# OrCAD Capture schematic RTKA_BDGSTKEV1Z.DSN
size Custom
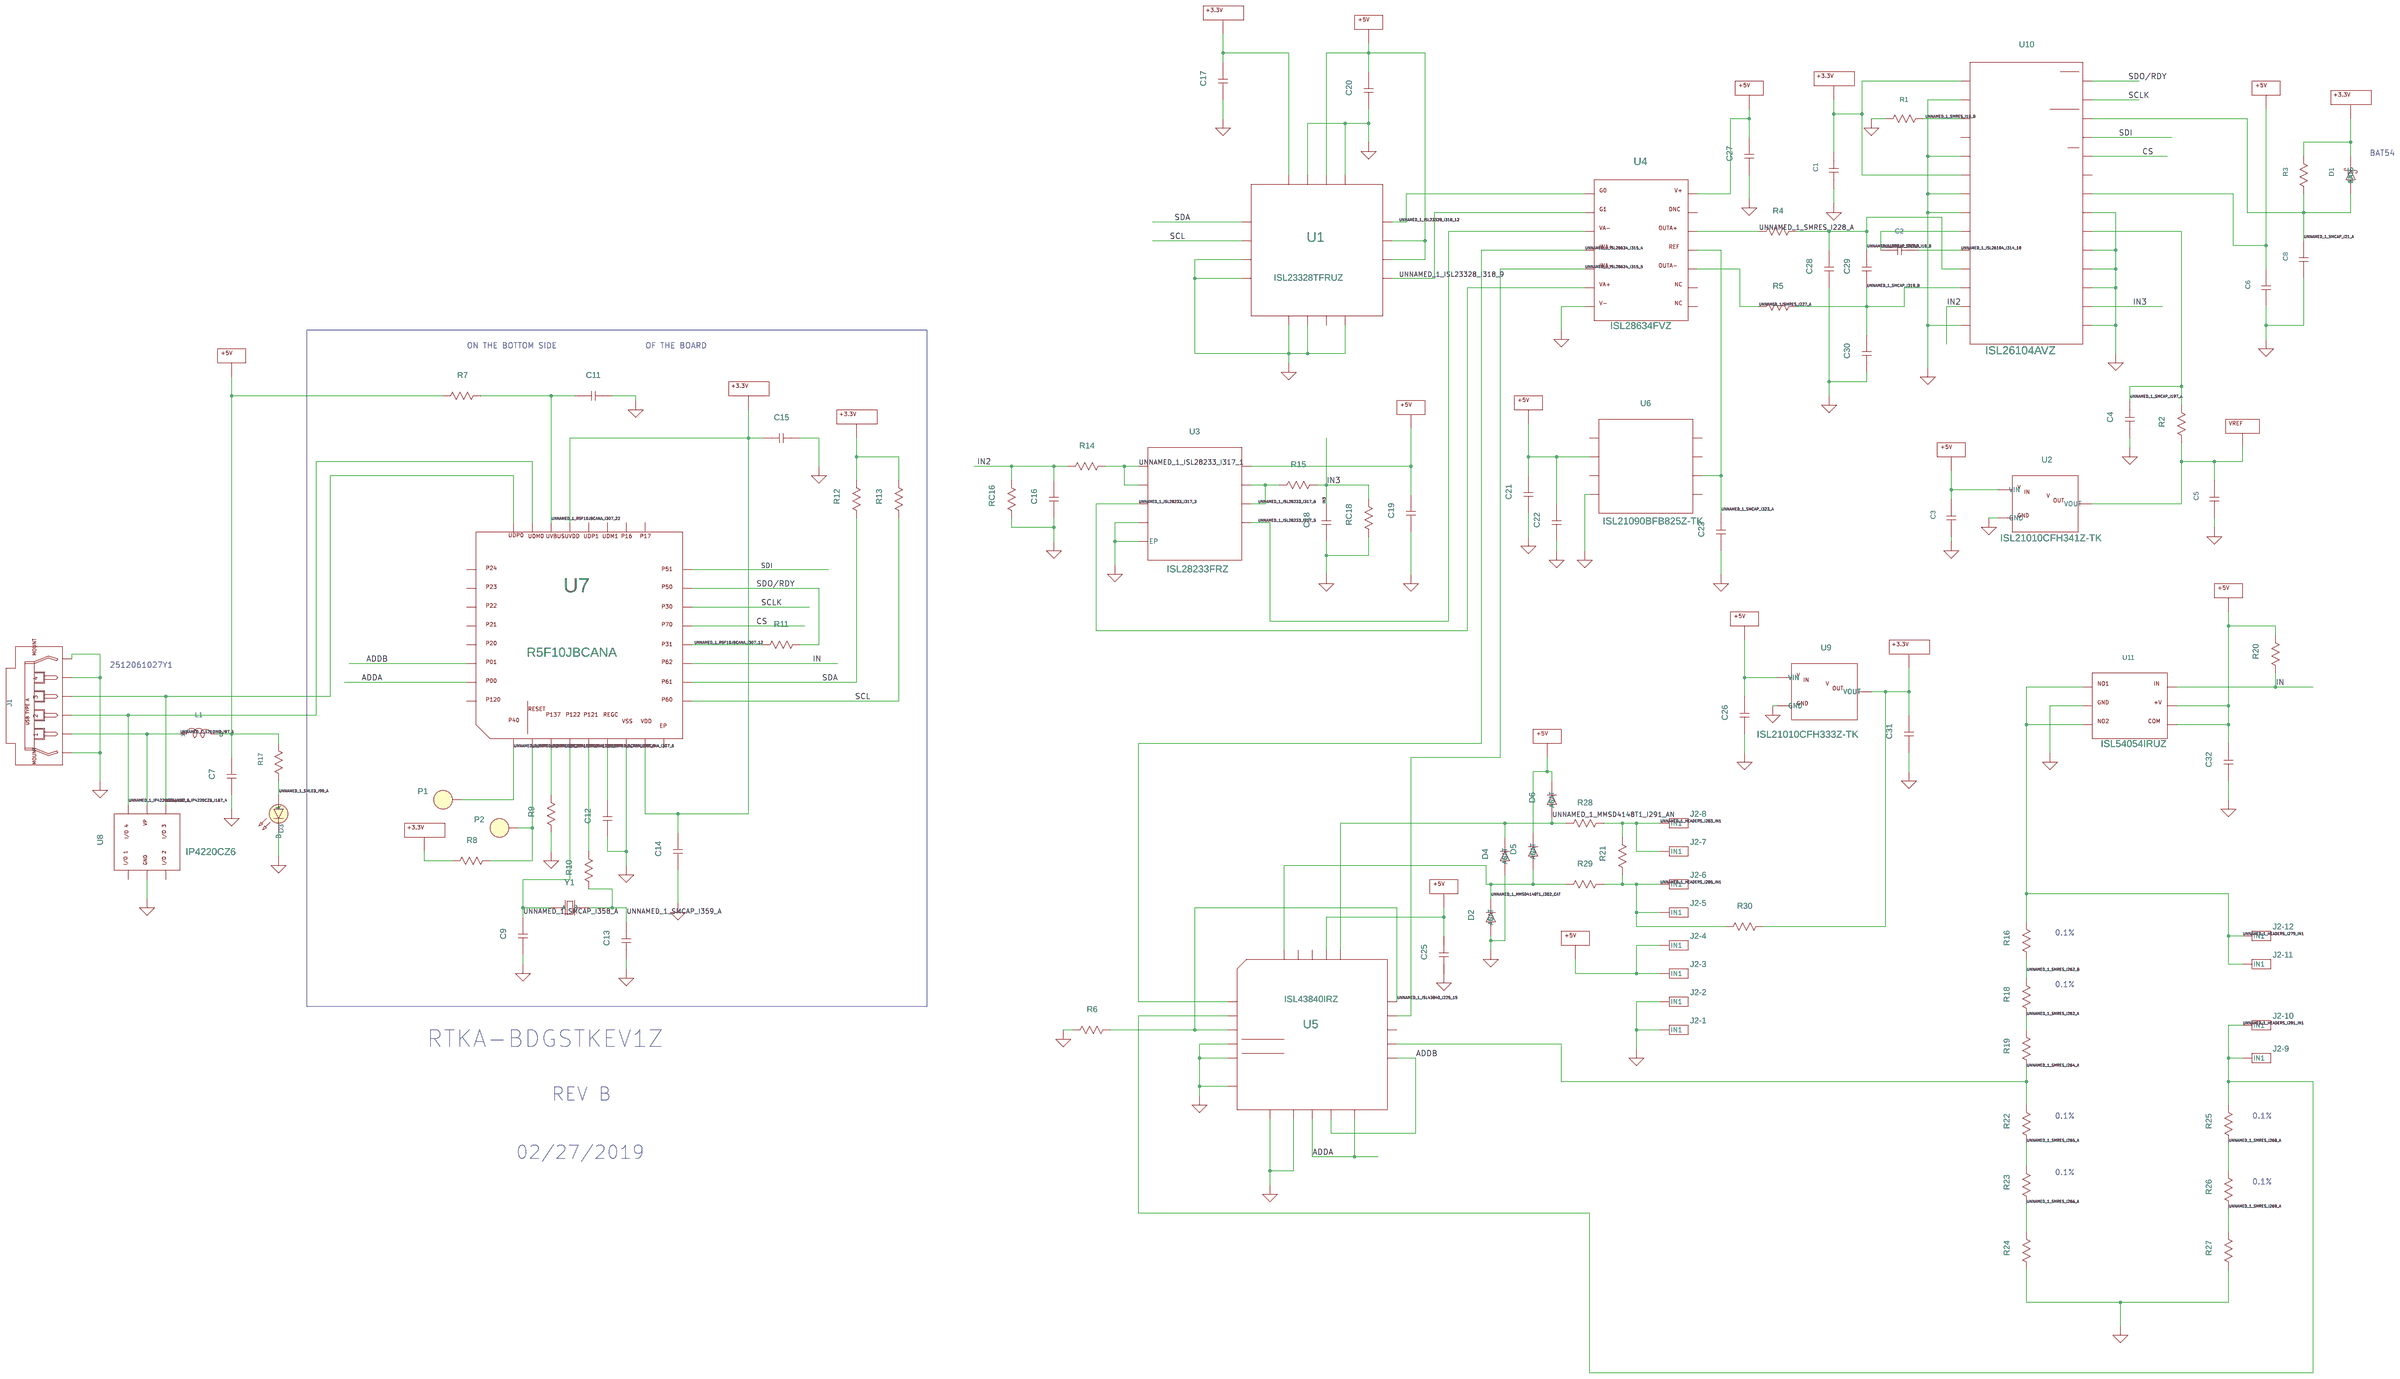
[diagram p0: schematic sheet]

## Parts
C1  0.01UF  [CAP_0402]
C2  0.1UF  [CAP_0402]
C3  1UF  [CAP_0603]
C4  10UF  [CAP_1206]
C5  0.1UF  [CAP_0402]
C6  0.01UF  [CAP_0402]
C7  4.7UF  [CAP_0805]
C8  2.2UF  [CAP_0805]
C9  10PF  [CAP_0402]
C11  1UF  [CAP_0603]
C12  1UF  [CAP_0603]
C13  10PF  [CAP_0402]
C14  0.1UF  [CAP_0402]
C15  0.33UF  [CAP_0603]
C16  0.1UF  [CAP_0402]
C17  0.1UF  [CAP_0402]
C18  0.1UF  [CAP_0402]
C19  0.1UF  [CAP_0402]
C20  0.1UF  [CAP_0402]
C21  10UF  [CAP_0805]
C22  0.1UF  [CAP_0402]
C23  0.1UF  [CAP_0402]
C25  0.01UF  [CAP_0402]
C26  1UF  [CAP_0603]
C27  0.1UF  [CAP_0402]
C28  0.1UF  [CAP_0402]
C29  0.1UF  [CAP_0402]
C30  0.1UF  [CAP_0402]
C31  0.1UF  [CAP_0402]
C32  0.1UF  [CAP_0402]
D1  SM_SCHOTTKY  [SOT23]
D2  MMSD4148T1  [SOD123]
D3  SM_LED  [DIA_LED1206]
D4  MMSD4148T1  [SOD123]
D5  MMSD4148T1  [SOD123]
D6  MMSD4148T1  [SOD123]
J1  USB_A  [CON_USB_MOLEX_480371000]
J2  HEADERS  [CON_HDR_90151-3X12]  (sections -1,-10,-11,-12,-2,-3,-4,-5,-6,-7,-8,-9)
L1  TBD  [SM1210]
P1  SINGLE  [PAD-50]
P2  SINGLE  [PAD-50]
R1  0  [RES_0402]
R2  100  [RES_0402]
R3  1K  [RES_0402]
R4  49.9  [RES_0402]
R5  49.9  [RES_0402]
R6  0  [RES_0402]
R7  100  [RES_0402]
R8  10K  [RES_0402]
R9  10K  [RES_0402]
R10  221  [RES_0402]
R11  0  [RES_0402]
R12  4.99K  [RES_0402]
R13  4.99K  [RES_0402]
R14  49.9  [RES_0402]
R15  49.9  [RES_0402]
R16  249  [RES_0805]
R17  3K  [RES_0603]
R18  100  [RES_0805]
R19  1  [RES_0805]
R20  4.99K  [RES_0402]
R21  499  [RES_0805]
R22  249  [RES_0805]
R23  100  [RES_0805]
R24  1  [RES_0805]
R25  249  [RES_0805]
R26  100  [RES_0805]
R27  1  [RES_0805]
R28  10K  [RES_0402]
R29  10K  [RES_0402]
R30  0  [RES_0402]
RC16  4.99K  [RES_0402]
RC18  4.99K  [RES_0402]
U1  ISL23328  [UTQFN16_102X71_157]
U2  ISL21010  [SOT23-3]
U3  ISL28233  [DFN8_118X118_256_EP2]
U4  ISL28634  [TSSOP14_173_256_V2]
U5  ISL43840  [QFN20_157X157_197_EP]
U6  ISL21090  [SOIC8_150_50E]
U7  R5F10JBCANA  [QFN32_197X197_197_EPA2]
U8  IP4220CZ6  [SOT457]
U9  ISL21010  [SOT23-3]
U10  ISL26104  [TSSOP28_173_256]
U11  ISL54054  [UTDFN6_47X39_157_A]
Y1  SM_CRYSTAL  [XTAL_NX5032GA]

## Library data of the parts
C1 = SM_CAP: CDS_LIB: capacitors; CDS_PART_NAME: SM_CAP_0402-H1044-00103-16V10,B; CDS_PHYS_PART_NAME: SM_CAP_0402-H1044-00103-16V10,B; DRAWING: @ISLTHERMO_STKEV1Z_LIB.RTKA_BDGSTKEV1Z(SCH_1):PAGE1; PACK_TYPE: 0402; PART_NUMBER: H1044-00103-16V10; PHYS_PAGE: 1; RATED_VOLTAGE: 16V; ROT: 1; TOLERANCE: 10%; VER: 1; XY: (5000,4625)
C2 = SM_CAP: CDS_LIB: capacitors; CDS_PART_NAME: SM_CAP_0402-H1044-00104-16V10,B; CDS_PHYS_PART_NAME: SM_CAP_0402-H1044-00104-16V10,B; DRAWING: @ISLTHERMO_STKEV1Z_LIB.RTKA_BDGSTKEV1Z(SCH_1):PAGE1; PACK_TYPE: 0402; PART_NUMBER: H1044-00104-16V10; PHYS_PAGE: 1; RATED_VOLTAGE: 16V; ROT: 0; TOLERANCE: 10%; VER: 1; XY: (5350,4200)
C3 = SM_CAP: CDS_LIB: capacitors; CDS_PART_NAME: SM_CAP_0603-H1045-00105-16V20,B; CDS_PHYS_PART_NAME: SM_CAP_0603-H1045-00105-16V20,B; DRAWING: @ISLTHERMO_STKEV1Z_LIB.RTKA_BDGSTKEV1Z(SCH_1):PAGE1; PACK_TYPE: 0603; PART_NUMBER: H1045-00105-16V20; PHYS_PAGE: 1; RATED_VOLTAGE: 16V; ROT: 1; TOLERANCE: 20%; VER: 1; XY: (5625,2775)
C4 = SM_CAP: CDS_LIB: capacitors; CDS_PART_NAME: SM_CAP_1206-H1065-00106-16V10,B; CDS_PHYS_PART_NAME: SM_CAP_1206-H1065-00106-16V10,B; DRAWING: @ISLTHERMO_STKEV1Z_LIB.RTKA_BDGSTKEV1Z(SCH_1):PAGE1; PACK_TYPE: 1206; PART_NUMBER: H1065-00106-16V10; PHYS_PAGE: 1; RATED_VOLTAGE: 16V; ROT: 1; TOLERANCE: 10%; VER: 1; XY: (6575,3300)
C5 = SM_CAP: CDS_LIB: capacitors; CDS_PART_NAME: SM_CAP_0402-H1044-00104-16V10,B; CDS_PHYS_PART_NAME: SM_CAP_0402-H1044-00104-16V10,B; DRAWING: @ISLTHERMO_STKEV1Z_LIB.RTKA_BDGSTKEV1Z(SCH_1):PAGE1; PACK_TYPE: 0402; PART_NUMBER: H1044-00104-16V10; PHYS_PAGE: 1; RATED_VOLTAGE: 16V; ROT: 1; TOLERANCE: 10%; VER: 1; XY: (7025,2875)
C6 = SM_CAP: CDS_LIB: capacitors; CDS_PART_NAME: SM_CAP_0402-H1044-00103-16V10,B; CDS_PHYS_PART_NAME: SM_CAP_0402-H1044-00103-16V10,B; DRAWING: @ISLTHERMO_STKEV1Z_LIB.RTKA_BDGSTKEV1Z(SCH_1):PAGE1; PACK_TYPE: 0402; PART_NUMBER: H1044-00103-16V10; PHYS_PAGE: 1; RATED_VOLTAGE: 16V; ROT: 1; TOLERANCE: 10%; VER: 1; XY: (7300,4000)
C7 = SM_CAP: CDS_LIB: capacitors; CDS_PART_NAME: SM_CAP_0805-GRM21BR71C475KA73LB; CDS_PHYS_PART_NAME: SM_CAP_0805-GRM21BR71C475KA73LB; DRAWING: @ISLTHERMO_STKEV1Z_LIB.RTKA_BDGSTKEV1Z(SCH_1):PAGE1; PACK_TYPE: 0805; PART_NUMBER: GRM21BR71C475KA73L; PHYS_PAGE: 1; RATED_VOLTAGE: 16V; ROT: 1; TOLERANCE: 10%; VER: 1; XY: (-3525,1400)
C8 = SM_CAP: CDS_LIB: capacitors; CDS_PART_NAME: SM_CAP_0805-H1046-00225-16V10,B; CDS_PHYS_PART_NAME: SM_CAP_0805-H1046-00225-16V10,B; DRAWING: @ISLTHERMO_STKEV1Z_LIB.RTKA_BDGSTKEV1Z(SCH_1):PAGE1; PACK_TYPE: 0805; PART_NUMBER: H1046-00225-16V10; PHYS_PAGE: 1; RATED_VOLTAGE: 16V; ROT: 1; TOLERANCE: 10%; VER: 1; XY: (7500,4150)
C9 = SM_CAP: CDS_LIB: capacitors; CDS_PART_NAME: SM_CAP_0402-H1044-00100-50V10,B; CDS_PHYS_PART_NAME: SM_CAP_0402-H1044-00100-50V10,B; DRAWING: @ISLTHERMO_STKEV1Z_LIB.RTKA_BDGSTKEV1Z(SCH_1):PAGE1; PACK_TYPE: 0402; PART_NUMBER: H1044-00100-50V10; PHYS_PAGE: 1; RATED_VOLTAGE: 50V; ROT: 1; TOLERANCE: 10%; VER: 1; XY: (-1975,550)
C11 = SM_CAP: CDS_LIB: capacitors; CDS_PART_NAME: SM_CAP_0603-H1045-00105-16V20,B; CDS_PHYS_PART_NAME: SM_CAP_0603-H1045-00105-16V20,B; DRAWING: @ISLTHERMO_STKEV1Z_LIB.RTKA_BDGSTKEV1Z(SCH_1):PAGE1; PACK_TYPE: 0603; PART_NUMBER: H1045-00105-16V20; PHYS_PAGE: 1; RATED_VOLTAGE: 16V; ROT: 0; TOLERANCE: 20%; VER: 1; XY: (-1600,3425)
C12 = SM_CAP: CDS_LIB: capacitors; CDS_PART_NAME: SM_CAP_0603-H1045-00105-16V20,B; CDS_PHYS_PART_NAME: SM_CAP_0603-H1045-00105-16V20,B; DRAWING: @ISLTHERMO_STKEV1Z_LIB.RTKA_BDGSTKEV1Z(SCH_1):PAGE1; PACK_TYPE: 0603; PART_NUMBER: H1045-00105-16V20; PHYS_PAGE: 1; RATED_VOLTAGE: 16V; ROT: 1; TOLERANCE: 20%; VER: 1; XY: (-1525,1175)
C13 = SM_CAP: CDS_LIB: capacitors; CDS_PART_NAME: SM_CAP_0402-H1044-00100-50V10,B; CDS_PHYS_PART_NAME: SM_CAP_0402-H1044-00100-50V10,B; DRAWING: @ISLTHERMO_STKEV1Z_LIB.RTKA_BDGSTKEV1Z(SCH_1):PAGE1; PACK_TYPE: 0402; PART_NUMBER: H1044-00100-50V10; PHYS_PAGE: 1; RATED_VOLTAGE: 50V; ROT: 1; TOLERANCE: 10%; VER: 1; XY: (-1425,525)
C14 = SM_CAP: CDS_LIB: capacitors; CDS_PART_NAME: SM_CAP_0402-H1044-00104-16V10,B; CDS_PHYS_PART_NAME: SM_CAP_0402-H1044-00104-16V10,B; DRAWING: @ISLTHERMO_STKEV1Z_LIB.RTKA_BDGSTKEV1Z(SCH_1):PAGE1; PACK_TYPE: 0402; PART_NUMBER: H1044-00104-16V10; PHYS_PAGE: 1; RATED_VOLTAGE: 16V; ROT: 1; TOLERANCE: 10%; VER: 1; XY: (-1150,1000)
C15 = SM_CAP: CDS_LIB: capacitors; CDS_PART_NAME: SM_CAP_0603-H1045-00334-25V10,B; CDS_PHYS_PART_NAME: SM_CAP_0603-H1045-00334-25V10,B; DRAWING: @ISLTHERMO_STKEV1Z_LIB.RTKA_BDGSTKEV1Z(SCH_1):PAGE1; PACK_TYPE: 0603; PART_NUMBER: H1045-00334-25V10; PHYS_PAGE: 1; RATED_VOLTAGE: 25V; ROT: 0; TOLERANCE: 10%; VER: 1; XY: (-600,3200)
C16 = SM_CAP: CDS_LIB: capacitors; CDS_PART_NAME: SM_CAP_0402-H1044-00104-16V10,B; CDS_PHYS_PART_NAME: SM_CAP_0402-H1044-00104-16V10,B; DRAWING: @ISLTHERMO_STKEV1Z_LIB.RTKA_BDGSTKEV1Z(SCH_1):PAGE1; PACK_TYPE: 0402; PART_NUMBER: H1044-00104-16V10; PHYS_PAGE: 1; RATED_VOLTAGE: 16V; ROT: 1; TOLERANCE: 10%; VER: 1; XY: (850,2875)
C17 = SM_CAP: CDS_LIB: capacitors; CDS_PART_NAME: SM_CAP_0402-H1044-00104-16V10,B; CDS_PHYS_PART_NAME: SM_CAP_0402-H1044-00104-16V10,B; DRAWING: @ISLTHERMO_STKEV1Z_LIB.RTKA_BDGSTKEV1Z(SCH_1):PAGE1; PACK_TYPE: 0402; PART_NUMBER: H1044-00104-16V10; PHYS_PAGE: 1; RATED_VOLTAGE: 16V; ROT: 1; TOLERANCE: 10%; VER: 1; XY: (1750,5100)
C18 = SM_CAP: CDS_LIB: capacitors; CDS_PART_NAME: SM_CAP_0402-H1044-00104-16V10,B; CDS_PHYS_PART_NAME: SM_CAP_0402-H1044-00104-16V10,B; DRAWING: @ISLTHERMO_STKEV1Z_LIB.RTKA_BDGSTKEV1Z(SCH_1):PAGE1; PACK_TYPE: 0402; PART_NUMBER: H1044-00104-16V10; PHYS_PAGE: 1; RATED_VOLTAGE: 16V; ROT: 1; TOLERANCE: 10%; VER: 1; XY: (2300,2750)
C19 = SM_CAP: CDS_LIB: capacitors; CDS_PART_NAME: SM_CAP_0402-H1044-00104-16V10,B; CDS_PHYS_PART_NAME: SM_CAP_0402-H1044-00104-16V10,B; DRAWING: @ISLTHERMO_STKEV1Z_LIB.RTKA_BDGSTKEV1Z(SCH_1):PAGE1; PACK_TYPE: 0402; PART_NUMBER: H1044-00104-16V10; PHYS_PAGE: 1; RATED_VOLTAGE: 16V; ROT: 1; TOLERANCE: 10%; VER: 1; XY: (2750,2800)
C20 = SM_CAP: CDS_LIB: capacitors; CDS_PART_NAME: SM_CAP_0402-H1044-00104-16V10,B; CDS_PHYS_PART_NAME: SM_CAP_0402-H1044-00104-16V10,B; DRAWING: @ISLTHERMO_STKEV1Z_LIB.RTKA_BDGSTKEV1Z(SCH_1):PAGE1; PACK_TYPE: 0402; PART_NUMBER: H1044-00104-16V10; PHYS_PAGE: 1; RATED_VOLTAGE: 16V; ROT: 1; TOLERANCE: 10%; VER: 1; XY: (2525,5050)
C21 = SM_CAP: CDS_LIB: capacitors; CDS_PART_NAME: SM_CAP_0805-C0805C106K8PACTU,1B; CDS_PHYS_PART_NAME: SM_CAP_0805-C0805C106K8PACTU,1B; DRAWING: @ISLTHERMO_STKEV1Z_LIB.RTKA_BDGSTKEV1Z(SCH_1):PAGE1; PACK_TYPE: 0805; PART_NUMBER: C0805C106K8PACTU; PHYS_PAGE: 1; RATED_VOLTAGE: 10V; ROT: 1; TOLERANCE: 10%; VER: 1; XY: (3375,2900)
C22 = SM_CAP: CDS_LIB: capacitors; CDS_PART_NAME: SM_CAP_0402-H1044-00104-16V10,B; CDS_PHYS_PART_NAME: SM_CAP_0402-H1044-00104-16V10,B; DRAWING: @ISLTHERMO_STKEV1Z_LIB.RTKA_BDGSTKEV1Z(SCH_1):PAGE1; PACK_TYPE: 0402; PART_NUMBER: H1044-00104-16V10; PHYS_PAGE: 1; RATED_VOLTAGE: 16V; ROT: 1; TOLERANCE: 10%; VER: 1; XY: (3525,2750)
C23 = SM_CAP: CDS_LIB: capacitors; CDS_PART_NAME: SM_CAP_0402-H1044-00104-16V10,B; CDS_PHYS_PART_NAME: SM_CAP_0402-H1044-00104-16V10,B; DRAWING: @ISLTHERMO_STKEV1Z_LIB.RTKA_BDGSTKEV1Z(SCH_1):PAGE1; PACK_TYPE: 0402; PART_NUMBER: H1044-00104-16V10; PHYS_PAGE: 1; RATED_VOLTAGE: 16V; ROT: 1; TOLERANCE: 10%; VER: 1; XY: (4400,2700)
C25 = SM_CAP: CDS_LIB: capacitors; CDS_PART_NAME: SM_CAP_0402-H1044-00103-16V10,B; CDS_PHYS_PART_NAME: SM_CAP_0402-H1044-00103-16V10,B; DRAWING: @ISLTHERMO_STKEV1Z_LIB.RTKA_BDGSTKEV1Z(SCH_1):PAGE1; PACK_TYPE: 0402; PART_NUMBER: H1044-00103-16V10; PHYS_PAGE: 1; RATED_VOLTAGE: 16V; ROT: 1; TOLERANCE: 10%; VER: 1; XY: (2925,450)
C26 = SM_CAP: CDS_LIB: capacitors; CDS_PART_NAME: SM_CAP_0603-H1045-00105-16V20,B; CDS_PHYS_PART_NAME: SM_CAP_0603-H1045-00105-16V20,B; DRAWING: @ISLTHERMO_STKEV1Z_LIB.RTKA_BDGSTKEV1Z(SCH_1):PAGE1; PACK_TYPE: 0603; PART_NUMBER: H1045-00105-16V20; PHYS_PAGE: 1; RATED_VOLTAGE: 16V; ROT: 1; TOLERANCE: 20%; VER: 1; XY: (4525,1725)
C27 = SM_CAP: CDS_LIB: capacitors; CDS_PART_NAME: SM_CAP_0402-H1044-00104-16V10,B; CDS_PHYS_PART_NAME: SM_CAP_0402-H1044-00104-16V10,B; DRAWING: @ISLTHERMO_STKEV1Z_LIB.RTKA_BDGSTKEV1Z(SCH_1):PAGE1; PACK_TYPE: 0402; PART_NUMBER: H1044-00104-16V10; PHYS_PAGE: 1; RATED_VOLTAGE: 16V; ROT: 1; TOLERANCE: 10%; VER: 1; XY: (4550,4700)
C28 = SM_CAP: CDS_LIB: capacitors; CDS_PART_NAME: SM_CAP_0402-H1044-00104-16V10,B; CDS_PHYS_PART_NAME: SM_CAP_0402-H1044-00104-16V10,B; DRAWING: @ISLTHERMO_STKEV1Z_LIB.RTKA_BDGSTKEV1Z(SCH_1):PAGE1; PACK_TYPE: 0402; PART_NUMBER: H1044-00104-16V10; PHYS_PAGE: 1; RATED_VOLTAGE: 16V; ROT: 1; TOLERANCE: 10%; VER: 1; XY: (4975,4100)
C29 = SM_CAP: CDS_LIB: capacitors; CDS_PART_NAME: SM_CAP_0402-H1044-00104-16V10,B; CDS_PHYS_PART_NAME: SM_CAP_0402-H1044-00104-16V10,B; DRAWING: @ISLTHERMO_STKEV1Z_LIB.RTKA_BDGSTKEV1Z(SCH_1):PAGE1; PACK_TYPE: 0402; PART_NUMBER: H1044-00104-16V10; PHYS_PAGE: 1; RATED_VOLTAGE: 16V; ROT: 1; TOLERANCE: 10%; VER: 1; XY: (5175,4100)
C30 = SM_CAP: CDS_LIB: capacitors; CDS_PART_NAME: SM_CAP_0402-H1044-00104-16V10,B; CDS_PHYS_PART_NAME: SM_CAP_0402-H1044-00104-16V10,B; DRAWING: @ISLTHERMO_STKEV1Z_LIB.RTKA_BDGSTKEV1Z(SCH_1):PAGE1; PACK_TYPE: 0402; PART_NUMBER: H1044-00104-16V10; PHYS_PAGE: 1; RATED_VOLTAGE: 16V; ROT: 1; TOLERANCE: 10%; VER: 1; XY: (5175,3650)
C31 = SM_CAP: CDS_LIB: capacitors; CDS_PART_NAME: SM_CAP_0402-H1044-00104-16V10,B; CDS_PHYS_PART_NAME: SM_CAP_0402-H1044-00104-16V10,B; DRAWING: @ISLTHERMO_STKEV1Z_LIB.RTKA_BDGSTKEV1Z(SCH_1):PAGE1; PACK_TYPE: 0402; PART_NUMBER: H1044-00104-16V10; PHYS_PAGE: 1; RATED_VOLTAGE: 16V; ROT: 1; TOLERANCE: 10%; VER: 1; XY: (5400,1625)
C32 = SM_CAP: CDS_LIB: capacitors; CDS_PART_NAME: SM_CAP_0402-H1044-00104-16V10,B; CDS_PHYS_PART_NAME: SM_CAP_0402-H1044-00104-16V10,B; DRAWING: @ISLTHERMO_STKEV1Z_LIB.RTKA_BDGSTKEV1Z(SCH_1):PAGE1; PACK_TYPE: 0402; PART_NUMBER: H1044-00104-16V10; PHYS_PAGE: 1; RATED_VOLTAGE: 16V; ROT: 1; TOLERANCE: 10%; VER: 1; XY: (7100,1475)
D1 = SM_SCHOTTKY: CDS_LIB: diodes; CDS_PART_NAME: SM_SCHOTTKY_SINGLE-BAT54,SOT23A; CDS_PHYS_PART_NAME: SM_SCHOTTKY_SINGLE-BAT54,SOT23A; DRAWING: @ISLTHERMO_STKEV1Z_LIB.RTKA_BDGSTKEV1Z(SCH_1):PAGE1; PART_NUMBER: BAT54; PHYS_PAGE: 1; ROT: 1; VER: 9; XY: (7750,4600)
D2 = MMSD4148T1: CDS_LIB: diodes; CDS_PART_NAME: MMSD4148T1_SOD123-MMSD4148T1,SB; CDS_PHYS_PART_NAME: MMSD4148T1_SOD123-MMSD4148T1,SB; DRAWING: @ISLTHERMO_STKEV1Z_LIB.RTKA_BDGSTKEV1Z(SCH_1):PAGE1; PHYS_PAGE: 1; ROT: 1; VER: 1; XY: (3175,650)
D3 = SM_LED: CDS_LIB: diodes; CDS_PART_NAME: SM_LED_SMD-597-3311-407,DIA_LEB; CDS_PHYS_PART_NAME: SM_LED_SMD-597-3311-407,DIA_LEB; DRAWING: @ISLTHERMO_STKEV1Z_LIB.RTKA_BDGSTKEV1Z(SCH_1):PAGE1; PACK_TYPE: SMD; PART_NUMBER: 597-3311-407; PHYS_PAGE: 1; ROT: 3; VER: 1; XY: (-3275,1200)
D4 = MMSD4148T1: CDS_LIB: diodes; CDS_PART_NAME: MMSD4148T1_SOD123-MMSD4148T1,SB; CDS_PHYS_PART_NAME: MMSD4148T1_SOD123-MMSD4148T1,SB; DRAWING: @ISLTHERMO_STKEV1Z_LIB.RTKA_BDGSTKEV1Z(SCH_1):PAGE1; PHYS_PAGE: 1; ROT: 1; VER: 1; XY: (3250,975)
D5 = MMSD4148T1: CDS_LIB: diodes; CDS_PART_NAME: MMSD4148T1_SOD123-MMSD4148T1,SB; CDS_PHYS_PART_NAME: MMSD4148T1_SOD123-MMSD4148T1,SB; DRAWING: @ISLTHERMO_STKEV1Z_LIB.RTKA_BDGSTKEV1Z(SCH_1):PAGE1; PHYS_PAGE: 1; ROT: 1; VER: 1; XY: (3400,1000)
D6 = MMSD4148T1: CDS_LIB: diodes; CDS_PART_NAME: MMSD4148T1_SOD123-MMSD4148T1,SB; CDS_PHYS_PART_NAME: MMSD4148T1_SOD123-MMSD4148T1,SB; DRAWING: @ISLTHERMO_STKEV1Z_LIB.RTKA_BDGSTKEV1Z(SCH_1):PAGE1; PHYS_PAGE: 1; ROT: 1; VER: 1; XY: (3500,1275)
J1 = USB_A: CDS_LIB: connectors; CDS_PART_NAME: USB_A_MOLEX1-48037-1000,CON_USB; CDS_PHYS_PART_NAME: USB_A_MOLEX1-48037-1000,CON_USB; DRAWING: @ISLTHERMO_STKEV1Z_LIB.RTKA_BDGSTKEV1Z(SCH_1):PAGE1; PART_NUMBER: 48037-1000; PHYS_PAGE: 1; ROT: 1; SEC_TYPE: MOLEX1; VER: 3; XY: (-4575,1775)
J2 = HEADERS: CDS_LIB: connectors; CDS_PART_NAME: HEADERS_12-90151-3X12,CON_HDR_B; CDS_PHYS_PART_NAME: HEADERS_12-90151-3X12,CON_HDR_B; DRAWING: @ISLTHERMO_STKEV1Z_LIB.RTKA_BDGSTKEV1Z(SCH_1):PAGE1; PACK_TYPE: 12; PART_NUMBER: 90151-3X12; PHYS_PAGE: 1; ROT: 2; SEC_TYPE: 12; VER: 1; XY: (7275,550)
L1 = 1210_IND: CDS_LIB: inductors; CDS_PART_NAME: IND1210_SMD-IND1210-TBD,TBD,TBB; CDS_PHYS_PART_NAME: IND1210_SMD-IND1210-TBD,TBD,TBB; CHIPS_PART_NAME: IND1210; DRAWING: @ISLTHERMO_STKEV1Z_LIB.RTKA_BDGSTKEV1Z(SCH_1):PAGE1; PACK_TYPE: SMD; PART_NUMBER: IND1210-TBD; PHYS_PAGE: 1; ROT: 0; VER: 1; XY: (-3700,1625)
P1 = SINGLE: CDS_LIB: pads; CDS_PART_NAME: SINGLE_THOLE-PAD_50-DNP,PAD-50A; CDS_PHYS_PART_NAME: SINGLE_THOLE-PAD_50-DNP,PAD-50A; DRAWING: @ISLTHERMO_STKEV1Z_LIB.RTKA_BDGSTKEV1Z(SCH_1):PAGE1; PACK_TYPE: THOLE; PART_NUMBER: PAD_50-DNP; PHYS_PAGE: 1; ROT: 2; VER: 1; XY: (-2400,1275)
P2 = SINGLE: CDS_LIB: pads; CDS_PART_NAME: SINGLE_THOLE-PAD_50-DNP,PAD-50A; CDS_PHYS_PART_NAME: SINGLE_THOLE-PAD_50-DNP,PAD-50A; DRAWING: @ISLTHERMO_STKEV1Z_LIB.RTKA_BDGSTKEV1Z(SCH_1):PAGE1; PACK_TYPE: THOLE; PART_NUMBER: PAD_50-DNP; PHYS_PAGE: 1; ROT: 2; VER: 1; XY: (-2100,1125)
R1 = SM_RES: CDS_LIB: resistors; CDS_PART_NAME: SM_RES_0402-H2510-00R00-1/16W,B; CDS_PHYS_PART_NAME: SM_RES_0402-H2510-00R00-1/16W,B; DRAWING: @ISLTHERMO_STKEV1Z_LIB.RTKA_BDGSTKEV1Z(SCH_1):PAGE1; PACK_TYPE: 0402; PART_NUMBER: H2510-00R00-1/16W; PHYS_PAGE: 1; RATED_POWER: 1/16W; TOLERANCE: 0%; VER: 1; XY: (5375,4900)
R2 = SM_RES: CDS_LIB: resistors; CDS_PART_NAME: SM_RES_0402-H2510-01000-1/16W1B; CDS_PHYS_PART_NAME: SM_RES_0402-H2510-01000-1/16W1B; DRAWING: @ISLTHERMO_STKEV1Z_LIB.RTKA_BDGSTKEV1Z(SCH_1):PAGE1; PACK_TYPE: 0402; PART_NUMBER: H2510-01000-1/16W1; PHYS_PAGE: 1; RATED_POWER: 1/16W; ROT: 1; TOLERANCE: 1%; VER: 1; XY: (6850,3275)
R3 = SM_RES: CDS_LIB: resistors; CDS_PART_NAME: SM_RES_0402-H2510-01001-1/16W1B; CDS_PHYS_PART_NAME: SM_RES_0402-H2510-01001-1/16W1B; DRAWING: @ISLTHERMO_STKEV1Z_LIB.RTKA_BDGSTKEV1Z(SCH_1):PAGE1; PACK_TYPE: 0402; PART_NUMBER: H2510-01001-1/16W1; PHYS_PAGE: 1; RATED_POWER: 1/16W; ROT: 1; TOLERANCE: 1%; VER: 1; XY: (7500,4600)
R4 = SM_RES: CDS_LIB: resistors; CDS_PART_NAME: SM_RES_0402-H2510-049R9-1/16W1B; CDS_PHYS_PART_NAME: SM_RES_0402-H2510-049R9-1/16W1B; DRAWING: @ISLTHERMO_STKEV1Z_LIB.RTKA_BDGSTKEV1Z(SCH_1):PAGE1; PACK_TYPE: 0402; PART_NUMBER: H2510-049R9-1/16W1; PHYS_PAGE: 1; RATED_POWER: 1/16W; ROT: 0; TOLERANCE: 1%; VER: 1; XY: (4700,4300)
R5 = SM_RES: CDS_LIB: resistors; CDS_PART_NAME: SM_RES_0402-H2510-049R9-1/16W1B; CDS_PHYS_PART_NAME: SM_RES_0402-H2510-049R9-1/16W1B; DRAWING: @ISLTHERMO_STKEV1Z_LIB.RTKA_BDGSTKEV1Z(SCH_1):PAGE1; PACK_TYPE: 0402; PART_NUMBER: H2510-049R9-1/16W1; PHYS_PAGE: 1; RATED_POWER: 1/16W; ROT: 0; TOLERANCE: 1%; VER: 1; XY: (4700,3900)
R6 = SM_RES: CDS_LIB: resistors; CDS_PART_NAME: SM_RES_0402-H2510-00R00-1/16W,B; CDS_PHYS_PART_NAME: SM_RES_0402-H2510-00R00-1/16W,B; DRAWING: @ISLTHERMO_STKEV1Z_LIB.RTKA_BDGSTKEV1Z(SCH_1):PAGE1; PACK_TYPE: 0402; PART_NUMBER: H2510-00R00-1/16W; PHYS_PAGE: 1; RATED_POWER: 1/16W; TOLERANCE: 0%; VER: 1; XY: (1050,50)
R7 = SM_RES: CDS_LIB: resistors; CDS_PART_NAME: SM_RES_0402-H2510-01000-1/16W1B; CDS_PHYS_PART_NAME: SM_RES_0402-H2510-01000-1/16W1B; DRAWING: @ISLTHERMO_STKEV1Z_LIB.RTKA_BDGSTKEV1Z(SCH_1):PAGE1; PACK_TYPE: 0402; PART_NUMBER: H2510-01000-1/16W1; PHYS_PAGE: 1; RATED_POWER: 1/16W; ROT: 0; TOLERANCE: 1%; VER: 1; XY: (-2300,3425)
R8 = SM_RES: CDS_LIB: resistors; CDS_PART_NAME: SM_RES_0402-H2510-01002-1/16W1B; CDS_PHYS_PART_NAME: SM_RES_0402-H2510-01002-1/16W1B; DRAWING: @ISLTHERMO_STKEV1Z_LIB.RTKA_BDGSTKEV1Z(SCH_1):PAGE1; PACK_TYPE: 0402; PART_NUMBER: H2510-01002-1/16W1; PHYS_PAGE: 1; RATED_POWER: 1/16W; ROT: 0; TOLERANCE: 1%; VER: 1; XY: (-2250,950)
R9 = SM_RES: CDS_LIB: resistors; CDS_PART_NAME: SM_RES_0402-H2510-01002-1/16W1B; CDS_PHYS_PART_NAME: SM_RES_0402-H2510-01002-1/16W1B; DRAWING: @ISLTHERMO_STKEV1Z_LIB.RTKA_BDGSTKEV1Z(SCH_1):PAGE1; PACK_TYPE: 0402; PART_NUMBER: H2510-01002-1/16W1; PHYS_PAGE: 1; RATED_POWER: 1/16W; ROT: 1; TOLERANCE: 1%; VER: 1; XY: (-1825,1200)
R10 = SM_RES: CDS_LIB: resistors; CDS_PART_NAME: SM_RES_0402-H2510-02210-1/16W1B; CDS_PHYS_PART_NAME: SM_RES_0402-H2510-02210-1/16W1B; DRAWING: @ISLTHERMO_STKEV1Z_LIB.RTKA_BDGSTKEV1Z(SCH_1):PAGE1; PACK_TYPE: 0402; PART_NUMBER: H2510-02210-1/16W1; PHYS_PAGE: 1; RATED_POWER: 1/16W; ROT: 1; TOLERANCE: 1%; VER: 1; XY: (-1625,900)
R11 = SM_RES: CDS_LIB: resistors; CDS_PART_NAME: SM_RES_0402-H2510-00R00-1/16W,B; CDS_PHYS_PART_NAME: SM_RES_0402-H2510-00R00-1/16W,B; DRAWING: @ISLTHERMO_STKEV1Z_LIB.RTKA_BDGSTKEV1Z(SCH_1):PAGE1; PACK_TYPE: 0402; PART_NUMBER: H2510-00R00-1/16W; PHYS_PAGE: 1; RATED_POWER: 1/16W; TOLERANCE: 0%; VER: 1; XY: (-600,2100)
R12 = SM_RES: CDS_LIB: resistors; CDS_PART_NAME: SM_RES_0402-H2510-04991-1/16W1B; CDS_PHYS_PART_NAME: SM_RES_0402-H2510-04991-1/16W1B; DRAWING: @ISLTHERMO_STKEV1Z_LIB.RTKA_BDGSTKEV1Z(SCH_1):PAGE1; PACK_TYPE: 0402; PART_NUMBER: H2510-04991-1/16W1; PHYS_PAGE: 1; RATED_POWER: 1/16W; ROT: 1; TOLERANCE: 1%; VER: 1; XY: (-200,2875)
R13 = SM_RES: CDS_LIB: resistors; CDS_PART_NAME: SM_RES_0402-H2510-04991-1/16W1B; CDS_PHYS_PART_NAME: SM_RES_0402-H2510-04991-1/16W1B; DRAWING: @ISLTHERMO_STKEV1Z_LIB.RTKA_BDGSTKEV1Z(SCH_1):PAGE1; PACK_TYPE: 0402; PART_NUMBER: H2510-04991-1/16W1; PHYS_PAGE: 1; RATED_POWER: 1/16W; ROT: 1; TOLERANCE: 1%; VER: 1; XY: (25,2875)
R14 = SM_RES: CDS_LIB: resistors; CDS_PART_NAME: SM_RES_0402-H2510-049R9-1/16W1B; CDS_PHYS_PART_NAME: SM_RES_0402-H2510-049R9-1/16W1B; DRAWING: @ISLTHERMO_STKEV1Z_LIB.RTKA_BDGSTKEV1Z(SCH_1):PAGE1; PACK_TYPE: 0402; PART_NUMBER: H2510-049R9-1/16W1; PHYS_PAGE: 1; RATED_POWER: 1/16W; ROT: 0; TOLERANCE: 1%; VER: 1; XY: (1025,3050)
R15 = SM_RES: CDS_LIB: resistors; CDS_PART_NAME: SM_RES_0402-H2510-049R9-1/16W1B; CDS_PHYS_PART_NAME: SM_RES_0402-H2510-049R9-1/16W1B; DRAWING: @ISLTHERMO_STKEV1Z_LIB.RTKA_BDGSTKEV1Z(SCH_1):PAGE1; PACK_TYPE: 0402; PART_NUMBER: H2510-049R9-1/16W1; PHYS_PAGE: 1; RATED_POWER: 1/16W; ROT: 0; TOLERANCE: 1%; VER: 1; XY: (2150,2950)
R16 = SM_RES: CDS_LIB: resistors; CDS_PART_NAME: SM_RES_0805-H2512-02490-1/10W1B; CDS_PHYS_PART_NAME: SM_RES_0805-H2512-02490-1/10W1B; DRAWING: @ISLTHERMO_STKEV1Z_LIB.RTKA_BDGSTKEV1Z(SCH_1):PAGE1; PACK_TYPE: 0805; PART_NUMBER: H2512-02490-1/10W1; PHYS_PAGE: 1; RATED_POWER: 1/10W; ROT: 1; TOLERANCE: 1%; VER: 1; XY: (6025,525)
R17 = SM_RES: CDS_LIB: resistors; CDS_PART_NAME: SM_RES_0603-MCR03EZPFX3001,3K,B; CDS_PHYS_PART_NAME: SM_RES_0603-MCR03EZPFX3001,3K,B; DRAWING: @ISLTHERMO_STKEV1Z_LIB.RTKA_BDGSTKEV1Z(SCH_1):PAGE1; PACK_TYPE: 0603; PART_NUMBER: MCR03EZPFX3001; PHYS_PAGE: 1; RATED_POWER: 1/10W; ROT: 1; TOLERANCE: 1%; VER: 1; XY: (-3275,1475)
R18 = SM_RES: CDS_LIB: resistors; CDS_PART_NAME: SM_RES_0805-H2512-01000-1/10W1B; CDS_PHYS_PART_NAME: SM_RES_0805-H2512-01000-1/10W1B; DRAWING: @ISLTHERMO_STKEV1Z_LIB.RTKA_BDGSTKEV1Z(SCH_1):PAGE1; PACK_TYPE: 0805; PART_NUMBER: H2512-01000-1/10W1; PHYS_PAGE: 1; RATED_POWER: 1/10W; ROT: 1; TOLERANCE: 1%; VER: 1; XY: (6025,225)
R19 = SM_RES: CDS_LIB: resistors; CDS_PART_NAME: SM_RES_0805-H2512-00010-1/10W1B; CDS_PHYS_PART_NAME: SM_RES_0805-H2512-00010-1/10W1B; DRAWING: @ISLTHERMO_STKEV1Z_LIB.RTKA_BDGSTKEV1Z(SCH_1):PAGE1; PACK_TYPE: 0805; PART_NUMBER: H2512-00010-1/10W1; RATED_POWER: 1/10W; TOLERANCE: 1%; XY: (6025,-50)
R20 = SM_RES: CDS_LIB: resistors; CDS_PART_NAME: SM_RES_0402-H2510-04991-1/16W1B; CDS_PHYS_PART_NAME: SM_RES_0402-H2510-04991-1/16W1B; DRAWING: @ISLTHERMO_STKEV1Z_LIB.RTKA_BDGSTKEV1Z(SCH_1):PAGE1; PACK_TYPE: 0402; PART_NUMBER: H2510-04991-1/16W1; PHYS_PAGE: 1; RATED_POWER: 1/16W; ROT: 1; TOLERANCE: 1%; VER: 1; XY: (7350,2050)
R21 = SM_RES: CDS_LIB: resistors; CDS_PART_NAME: SM_RES_0805-H2512-04990-1/10W1B; CDS_PHYS_PART_NAME: SM_RES_0805-H2512-04990-1/10W1B; DRAWING: @ISLTHERMO_STKEV1Z_LIB.RTKA_BDGSTKEV1Z(SCH_1):PAGE1; PACK_TYPE: 0805; PART_NUMBER: H2512-04990-1/10W1; PHYS_PAGE: 1; RATED_POWER: 1/10W; ROT: 1; TOLERANCE: 1%; VER: 1; XY: (3875,975)
R22 = SM_RES: CDS_LIB: resistors; CDS_PART_NAME: SM_RES_0805-H2512-02490-1/10W1B; CDS_PHYS_PART_NAME: SM_RES_0805-H2512-02490-1/10W1B; DRAWING: @ISLTHERMO_STKEV1Z_LIB.RTKA_BDGSTKEV1Z(SCH_1):PAGE1; PACK_TYPE: 0805; PART_NUMBER: H2512-02490-1/10W1; PHYS_PAGE: 1; RATED_POWER: 1/10W; ROT: 1; TOLERANCE: 1%; VER: 1; XY: (6025,-450)
R23 = SM_RES: CDS_LIB: resistors; CDS_PART_NAME: SM_RES_0805-H2512-01000-1/10W1B; CDS_PHYS_PART_NAME: SM_RES_0805-H2512-01000-1/10W1B; DRAWING: @ISLTHERMO_STKEV1Z_LIB.RTKA_BDGSTKEV1Z(SCH_1):PAGE1; PACK_TYPE: 0805; PART_NUMBER: H2512-01000-1/10W1; PHYS_PAGE: 1; RATED_POWER: 1/10W; ROT: 1; TOLERANCE: 1%; VER: 1; XY: (6025,-775)
R24 = SM_RES: CDS_LIB: resistors; CDS_PART_NAME: SM_RES_0805-H2512-00010-1/10W1B; CDS_PHYS_PART_NAME: SM_RES_0805-H2512-00010-1/10W1B; DRAWING: @ISLTHERMO_STKEV1Z_LIB.RTKA_BDGSTKEV1Z(SCH_1):PAGE1; PACK_TYPE: 0805; PART_NUMBER: H2512-00010-1/10W1; RATED_POWER: 1/10W; TOLERANCE: 1%; XY: (6025,-1125)
R25 = SM_RES: CDS_LIB: resistors; CDS_PART_NAME: SM_RES_0805-H2512-02490-1/10W1B; CDS_PHYS_PART_NAME: SM_RES_0805-H2512-02490-1/10W1B; DRAWING: @ISLTHERMO_STKEV1Z_LIB.RTKA_BDGSTKEV1Z(SCH_1):PAGE1; PACK_TYPE: 0805; PART_NUMBER: H2512-02490-1/10W1; PHYS_PAGE: 1; RATED_POWER: 1/10W; ROT: 1; TOLERANCE: 1%; VER: 1; XY: (7100,-450)
R26 = SM_RES: CDS_LIB: resistors; CDS_PART_NAME: SM_RES_0805-H2512-01000-1/10W1B; CDS_PHYS_PART_NAME: SM_RES_0805-H2512-01000-1/10W1B; DRAWING: @ISLTHERMO_STKEV1Z_LIB.RTKA_BDGSTKEV1Z(SCH_1):PAGE1; PACK_TYPE: 0805; PART_NUMBER: H2512-01000-1/10W1; PHYS_PAGE: 1; RATED_POWER: 1/10W; ROT: 1; TOLERANCE: 1%; VER: 1; XY: (7100,-800)
R27 = SM_RES: CDS_LIB: resistors; CDS_PART_NAME: SM_RES_0805-H2512-00010-1/10W1B; CDS_PHYS_PART_NAME: SM_RES_0805-H2512-00010-1/10W1B; DRAWING: @ISLTHERMO_STKEV1Z_LIB.RTKA_BDGSTKEV1Z(SCH_1):PAGE1; PACK_TYPE: 0805; PART_NUMBER: H2512-00010-1/10W1; RATED_POWER: 1/10W; TOLERANCE: 1%; XY: (7100,-1125)
R28 = SM_RES: CDS_LIB: resistors; CDS_PART_NAME: SM_RES_0402-H2510-01002-1/16W1B; CDS_PHYS_PART_NAME: SM_RES_0402-H2510-01002-1/16W1B; DRAWING: @ISLTHERMO_STKEV1Z_LIB.RTKA_BDGSTKEV1Z(SCH_1):PAGE1; PACK_TYPE: 0402; PART_NUMBER: H2510-01002-1/16W1; PHYS_PAGE: 1; RATED_POWER: 1/16W; ROT: 0; TOLERANCE: 1%; VER: 1; XY: (3675,1150)
R29 = SM_RES: CDS_LIB: resistors; CDS_PART_NAME: SM_RES_0402-H2510-01002-1/16W1B; CDS_PHYS_PART_NAME: SM_RES_0402-H2510-01002-1/16W1B; DRAWING: @ISLTHERMO_STKEV1Z_LIB.RTKA_BDGSTKEV1Z(SCH_1):PAGE1; PACK_TYPE: 0402; PART_NUMBER: H2510-01002-1/16W1; PHYS_PAGE: 1; RATED_POWER: 1/16W; ROT: 0; TOLERANCE: 1%; VER: 1; XY: (3675,825)
R30 = SM_RES: CDS_LIB: resistors; CDS_PART_NAME: SM_RES_0402-H2510-00R00-1/16W,B; CDS_PHYS_PART_NAME: SM_RES_0402-H2510-00R00-1/16W,B; DRAWING: @ISLTHERMO_STKEV1Z_LIB.RTKA_BDGSTKEV1Z(SCH_1):PAGE1; PACK_TYPE: 0402; PART_NUMBER: H2510-00R00-1/16W; PHYS_PAGE: 1; RATED_POWER: 1/16W; TOLERANCE: 0%; VER: 1; XY: (4525,600)
RC16 = SM_RES: CDS_LIB: resistors; CDS_PART_NAME: SM_RES_0402-H2510-04991-1/16W1B; CDS_PHYS_PART_NAME: SM_RES_0402-H2510-04991-1/16W1B; DRAWING: @ISLTHERMO_STKEV1Z_LIB.RTKA_BDGSTKEV1Z(SCH_1):PAGE1; PACK_TYPE: 0402; PART_NUMBER: H2510-04991-1/16W1; PHYS_PAGE: 1; RATED_POWER: 1/16W; ROT: 1; TOLERANCE: 1%; VER: 1; XY: (625,2875)
RC18 = SM_RES: CDS_LIB: resistors; CDS_PART_NAME: SM_RES_0402-H2510-04991-1/16W1B; CDS_PHYS_PART_NAME: SM_RES_0402-H2510-04991-1/16W1B; DRAWING: @ISLTHERMO_STKEV1Z_LIB.RTKA_BDGSTKEV1Z(SCH_1):PAGE1; PACK_TYPE: 0402; PART_NUMBER: H2510-04991-1/16W1; PHYS_PAGE: 1; RATED_POWER: 1/16W; ROT: 1; TOLERANCE: 1%; VER: 1; XY: (2525,2775)
U1 = ISL23328: CDS_LIB: potentiometers; CDS_PART_NAME: ISL23328_UTQFN16-ISL23328TFRUZB; CDS_PHYS_PART_NAME: ISL23328_UTQFN16-ISL23328TFRUZB; DRAWING: @ISLTHERMO_STKEV1Z_LIB.RTKA_BDGSTKEV1Z(SCH_1):PAGE1; PACK_TYPE: UTQFN16; PART_NUMBER: ISL23328TFRUZ; PHYS_PAGE: 1; ROT: 0; SEC_TYPE: UTQFN16; VER: 1; XY: (2250,4200)
U2 = ISL21010: CDS_LIB: voltrefs; CDS_PART_NAME: ISL21010_SOT23-3-ISL21010CFH34B; CDS_PHYS_PART_NAME: ISL21010_SOT23-3-ISL21010CFH34B; DRAWING: @ISLTHERMO_STKEV1Z_LIB.RTKA_BDGSTKEV1Z(SCH_1):PAGE1; PART_NUMBER: ISL21010CFH341Z-TK; PHYS_PAGE: 1; ROT: 0; VER: 1; XY: (6125,2850)
U3 = ISL28233: CDS_LIB: amplifiers; CDS_PART_NAME: ISL28233_TDFN8-ISL28233FRZ,DFNB; CDS_PHYS_PART_NAME: ISL28233_TDFN8-ISL28233FRZ,DFNB; DRAWING: @ISLTHERMO_STKEV1Z_LIB.RTKA_BDGSTKEV1Z(SCH_1):PAGE1; PACK_TYPE: TDFN8; PART_NUMBER: ISL28233FRZ; PHYS_PAGE: 1; ROT: 0; SEC_TYPE: TDFN8; VER: 1; XY: (1600,2850)
U4 = ISL28634: CDS_LIB: amplifiers; CDS_PART_NAME: ISL28634_TSSOP14-ISL28634FVZ,TB; CDS_PHYS_PART_NAME: ISL28634_TSSOP14-ISL28634FVZ,TB; DRAWING: @ISLTHERMO_STKEV1Z_LIB.RTKA_BDGSTKEV1Z(SCH_1):PAGE1; PACK_TYPE: TSSOP14; PART_NUMBER: ISL28634FVZ; PHYS_PAGE: 1; ROT: 0; SEC_TYPE: TSSOP14; VER: 1; XY: (3975,4200)
U5 = ISL43840: CDS_LIB: multiplexers; CDS_PART_NAME: ISL43840_20QFN-ISL43840IRZ,QFNB; CDS_PHYS_PART_NAME: ISL43840_20QFN-ISL43840IRZ,QFNB; DRAWING: @ISLTHERMO_STKEV1Z_LIB.RTKA_BDGSTKEV1Z(SCH_1):PAGE1; PACK_TYPE: 20QFN; PART_NUMBER: ISL43840IRZ; PHYS_PAGE: 1; ROT: 0; SEC_TYPE: 20QFN; VER: 1; XY: (2225,25)
U6 = ISL21090: CDS_LIB: voltrefs; CDS_PART_NAME: ISL21090_SOIC8-ISL21090BFB825ZB; CDS_PHYS_PART_NAME: ISL21090_SOIC8-ISL21090BFB825ZB; DRAWING: @ISLTHERMO_STKEV1Z_LIB.RTKA_BDGSTKEV1Z(SCH_1):PAGE1; PACK_TYPE: SOIC8; PART_NUMBER: ISL21090BFB825Z-TK; PHYS_PAGE: 1; ROT: 0; SEC_TYPE: SOIC8; VER: 1; XY: (4000,3050)
U7 = R5F10JBCANA: CDS_LIB: microcontrollers; CDS_PART_NAME: R5F10JBCANA_32HWQFN-R5F10JBCANB; CDS_PHYS_PART_NAME: R5F10JBCANA_32HWQFN-R5F10JBCANB; DRAWING: @ISLTHERMO_STKEV1Z_LIB.RTKA_BDGSTKEV1Z(SCH_1):PAGE1; PACK_TYPE: 32HWQFN; PHYS_PAGE: 1; ROT: 0; SEC_TYPE: 32HWQFN; VER: 2; XY: (-1675,2150)
U8 = IP4220CZ6: CDS_LIB: interface_logic; CDS_PART_NAME: IP4220CZ6_SOT457-IP4220CZ6,SOTB; CDS_PHYS_PART_NAME: IP4220CZ6_SOT457-IP4220CZ6,SOTB; DRAWING: @ISLTHERMO_STKEV1Z_LIB.RTKA_BDGSTKEV1Z(SCH_1):PAGE1; PHYS_PAGE: 1; ROT: 1; VER: 1; XY: (-3975,1050)
U9 = ISL21010: CDS_LIB: voltrefs; CDS_PART_NAME: ISL21010_SOT23-3-ISL21010CFH33B; CDS_PHYS_PART_NAME: ISL21010_SOT23-3-ISL21010CFH33B; DRAWING: @ISLTHERMO_STKEV1Z_LIB.RTKA_BDGSTKEV1Z(SCH_1):PAGE1; PART_NUMBER: ISL21010CFH333Z-TK; PHYS_PAGE: 1; ROT: 0; VER: 1; XY: (4950,1850)
U10 = ISL26104: CDS_LIB: converters; CDS_PART_NAME: ISL26104_TSSOP-ISL26104AVZ,TSSB; CDS_PHYS_PART_NAME: ISL26104_TSSOP-ISL26104AVZ,TSSB; DRAWING: @ISLTHERMO_STKEV1Z_LIB.RTKA_BDGSTKEV1Z(SCH_1):PAGE1; PACK_TYPE: TSSOP; PART_NUMBER: ISL26104AVZ; PHYS_PAGE: 1; ROT: 0; SEC_TYPE: TSSOP; VER: 1; XY: (6025,4450)
U11 = ISL54054: CDS_LIB: switches; CDS_PART_NAME: ISL54054_UTDFN6-ISL54054IRUZ,UB; CDS_PHYS_PART_NAME: ISL54054_UTDFN6-ISL54054IRUZ,UB; DRAWING: @ISLTHERMO_STKEV1Z_LIB.RTKA_BDGSTKEV1Z(SCH_1):PAGE1; PACK_TYPE: UTDFN6; PART_NUMBER: ISL54054IRUZ; PHYS_PAGE: 1; ROT: 0; SEC_TYPE: UTDFN6; VER: 1; XY: (6575,1775)
Y1 = SM_CRYSTAL: CDS_LIB: crystals; CDS_PART_NAME: SM_CRYSTAL_SM-NX5032GA-48.000MB; CDS_PHYS_PART_NAME: SM_CRYSTAL_SM-NX5032GA-48.000MB; DRAWING: @ISLTHERMO_STKEV1Z_LIB.RTKA_BDGSTKEV1Z(SCH_1):PAGE1; PACK_TYPE: SM; PART_NUMBER: NX5032GA-48.000M-LN-CD-1; PHYS_PAGE: 1; ROT: 0; VER: 1; XY: (-1725,700)

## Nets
+3.3V: C1.1(A) C14.1(A) C15.2(B) C17.1(A) C31.1(A) D1.3(CATS) R3.2(B) R8.1(A) R12.2(B) R13.2(B) R30.2(B) U1.16 U7.8 U7.21 U9.2(VOUT) U10.1 U10.6
+5V: C3.1(A) C6.1(A) C7.1(A) C19.1(A) C20.1(A) C21.1(A) C22.1(A) C25.1(A) C26.1(A) C27.1(A) C32.1(A) D5.1(CAT) D6.1(CAT) J2.9(IN1) J2.10(IN1) L1.2(B) R7.1(A) R17.2(B) R20.2(B) U1.10 U1.11 U1.14 U2.1(VIN) U3.8 U4.14 U5.17 U6.2 U9.1(VIN) U10.22 U11.4 U11.5
GND: C1.2(B) C3.2(B) C4.2(B) C5.2(B) C6.2(B) C7.2(B) C8.2(B) C9.2(B) C11.1(A) C12.2(B) C13.2(B) C14.2(B) C15.1(A) C16.2(B) C17.2(B) C18.2(B) C19.2(B) C20.2(B) C21.2(B) C22.2(B) C23.2(B) C25.2(B) C26.2(B) C27.2(B) C28.2(B) C30.2(B) C31.2(B) C32.2(B) D2.2(AN) D3.2(B) D4.2(AN) J1.4 J1.M1 J1.M2 J2.11(IN1) J2.12(IN1) R1.1(A) R6.1(A) R9.1(A) R24.1(A) R27.1(A) RC16.1(A) RC18.1(A) U1.3 U1.4 U1.5 U1.6 U1.8 U1.13 U1.15 U2.3(GND) U3.4 U3.9(EP) U4.7 U5.4 U5.5 U5.6 U5.7 U5.21 U6.4 U7.7 U8.2 U9.3(GND) U10.2 U10.5 U10.7 U10.8 U10.14 U10.15 U10.17 U10.18 U10.19 U10.21 U11.2
ADDA: U5.8 U5.10 U7.31
ADDB: U5.9 U5.11 U7.30
CS: U7.13 U10.24
IN: R20.1(A) U7.11 U11.6
IN2: C16.1(A) R14.1(A) RC16.2(B) U10.13
IN3: C18.1(A) R15.2(B) RC18.2(B) U10.16
SCL: R13.1(A) U1.2 U7.9
SCLK: U7.14 U10.27
SDA: R12.1(A) U1.1 U7.10
SDI: U7.16 U10.25
SDO/RDY: R11.2(B) U7.15 U10.28
UNNAMED_1_1210IND_I97_A: J1.1 L1.1(A) U8.5
UNNAMED_1_HEADERS_I279_IN1: J2.1(IN1) J2.2(IN1) R16.2(B) U11.1 U11.3
UNNAMED_1_HEADERS_I281_IN1: J2.3(IN1) J2.4(IN1) R25.2(B) U5.2
UNNAMED_1_HEADERS_I283_IN1: J2.5(IN1) J2.6(IN1) R21.2(B) R28.2(B)
UNNAMED_1_HEADERS_I285_IN1: J2.7(IN1) J2.8(IN1) R21.1(A) R29.2(B) R30.1(A)
UNNAMED_1_IP4220CZ6_I167_4: J1.3 U7.24 U8.4
UNNAMED_1_IP4220CZ6_I167_6: J1.2 U7.23 U8.6
UNNAMED_1_ISL23328_I318_9: U1.9 U4.2
UNNAMED_1_ISL23328_I318_12: U1.12 U4.1
UNNAMED_1_ISL26104_I314_10: C2.1(A) U10.10
UNNAMED_1_ISL28233_I317_1: R14.2(B) U3.1 U3.2
UNNAMED_1_ISL28233_I317_3: U3.3 U4.6
UNNAMED_1_ISL28233_I317_5: U3.5 U4.3
UNNAMED_1_ISL28233_I317_6: R15.1(A) U3.6 U3.7
UNNAMED_1_ISL28634_I315_4: U4.4 U5.1
UNNAMED_1_ISL28634_I315_5: U4.5 U5.14
UNNAMED_1_ISL43840_I225_15: R6.2(B) U5.3 U5.15
UNNAMED_1_MMSD4148T1_I291_AN: D4.1(CAT) D6.2(AN) R28.1(A) U5.16
UNNAMED_1_MMSD4148T1_I302_CAT: D2.1(CAT) D5.2(AN) R29.1(A) U5.20
UNNAMED_1_R5F10JBCANA_I307_1: P1.1(P) U7.1
UNNAMED_1_R5F10JBCANA_I307_2: P2.1(P) R8.2(B) U7.2
UNNAMED_1_R5F10JBCANA_I307_3: R9.2(B) U7.3
UNNAMED_1_R5F10JBCANA_I307_5: R10.2(B) U7.5
UNNAMED_1_R5F10JBCANA_I307_6: C12.1(A) U7.6
UNNAMED_1_R5F10JBCANA_I307_12: R11.1(A) U7.12
UNNAMED_1_R5F10JBCANA_I307_22: C11.2(B) R7.2(B) U7.22
UNNAMED_1_SMCAP_I18_B: C2.2(B) U10.9
UNNAMED_1_SMCAP_I21_A: C8.1(A) D1.1(ANS) R3.1(A) U10.26
UNNAMED_1_SMCAP_I197_A: C4.1(A) R2.2(B) U10.20
UNNAMED_1_SMCAP_I319_A: C28.1(A) C29.1(A) R4.2(B) U10.11
UNNAMED_1_SMCAP_I319_B: C29.2(B) C30.1(A) R5.2(B) U10.12
UNNAMED_1_SMCAP_I323_A: C23.1(A) U4.11 U6.6
UNNAMED_1_SMCAP_I358_A: C9.1(A) U7.4 Y1.1(A)
UNNAMED_1_SMCAP_I359_A: C13.1(A) R10.1(A) Y1.2(B)
UNNAMED_1_SMLED_I99_A: D3.1(A) R17.1(A)
UNNAMED_1_SMRES_I15_B: R1.2(B) U10.3
UNNAMED_1_SMRES_I227_A: R5.1(A) U4.10
UNNAMED_1_SMRES_I228_A: R4.1(A) U4.12
UNNAMED_1_SMRES_I262_A: R18.1(A) R19.2(B)
UNNAMED_1_SMRES_I262_B: R16.1(A) R18.2(B)
UNNAMED_1_SMRES_I264_A: R19.1(A) R22.2(B) U5.12
UNNAMED_1_SMRES_I265_A: R22.1(A) R23.2(B)
UNNAMED_1_SMRES_I266_A: R23.1(A) R24.2(B)
UNNAMED_1_SMRES_I268_A: R25.1(A) R26.2(B)
UNNAMED_1_SMRES_I269_A: R26.1(A) R27.2(B)
VREF: C5.1(A) R2.1(A) U2.2(VOUT)

Not connected (* = marked no-connect by the designer): U1 7; U4 8 9 13; U5 13 18 19; U6 1 3 5 7 8; U7 17 18 19 20 25 26 27 28 29 32 33; U8 1 3; U10 4 23

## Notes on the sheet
- BAT54
- ON THE BOTTOM SIDE
- OF THE BOARD
- 2512061027Y1
- 0.1%
- 0.1%
- RTKA-BDGSTKEV1Z
- REV B
- 0.1%
- 0.1%
- 02/27/2019
- 0.1%
- 0.1%
